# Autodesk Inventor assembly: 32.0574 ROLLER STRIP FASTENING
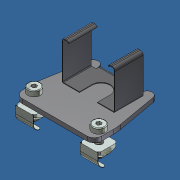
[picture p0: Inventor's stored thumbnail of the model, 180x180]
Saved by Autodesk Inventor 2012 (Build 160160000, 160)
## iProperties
Created: 2013-04
Part Number: 32.0574 ROLLER STRIP FASTENING
Document SubType Name: Assembly
Designer: Admin
Author: Admin
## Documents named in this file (5)
- C:\Andys Backup Data\ANDY'S INVENTOR\INVENTOR LIBRARIES\PARTS LIBRARY\KANBAN SYSTEMS\32.0574 ROLLER STRIP FASTENING.iam
- C:\Andys Backup Data\ANDY'S INVENTOR\INVENTOR LIBRARIES\PARTS LIBRARY\KANBAN SYSTEMS\SUBCOMPONENTS\32.0574 BASE PLATE.ipt
- C:\Andys Backup Data\ANDY'S INVENTOR\INVENTOR LIBRARIES\PARTS LIBRARY\KANBAN SYSTEMS\SUBCOMPONENTS\32.0574 CLIP.ipt
- C:\Andys Backup Data\ANDY'S INVENTOR\INVENTOR LIBRARIES\PARTS LIBRARY\FASTENING ELEMENTS\SCREWS CAP\21.1235 M5X16.ipt
- C:\Andys Backup Data\ANDY'S INVENTOR\INVENTOR LIBRARIES\PARTS LIBRARY\FASTENING ELEMENTS\NUTS\21.1320_2 M5 SQUARE NUT POS FXG.ipt
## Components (6 placed, 4 different names)
1. 32.0574 BASE PLATE:1 — Mate:1, Mate:2, Angle:1, Flush:1, Insert:1, Insert:2, Mate:5, Mate:6, Angle:2, Angle:3
2. 32.0574 CLIP:1 — Mate:1, Mate:2, Angle:1, Flush:1
3. 21.1235  M5 x 16:1 — Insert:1, Mate:3
4. 21.1235  M5 x 16:2 — Insert:2, Mate:4
5. 21.1320_2 M5 SQUARE NUT POS FXG:1 — Mate:3, Mate:5, Angle:3
6. 21.1320_2 M5 SQUARE NUT POS FXG:2 — Mate:4, Mate:6, Angle:2
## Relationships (12: Mate 6, Angle 3, Insert 2, Flush 1)
- Mate:1: 32.0574 BASE PLATE:1 ↔ 32.0574 CLIP:1
- Mate:2: 32.0574 BASE PLATE:1 ↔ 32.0574 CLIP:1
- Angle:1: 32.0574 BASE PLATE:1 ↔ 32.0574 CLIP:1
- Flush:1: 32.0574 BASE PLATE:1 ↔ 32.0574 CLIP:1
- Insert:1: 32.0574 BASE PLATE:1 ↔ 21.1235  M5 x 16:1
- Insert:2: 32.0574 BASE PLATE:1 ↔ 21.1235  M5 x 16:2
- Mate:3: 21.1235  M5 x 16:1 ↔ 21.1320_2 M5 SQUARE NUT POS FXG:1
- Mate:4: 21.1235  M5 x 16:2 ↔ 21.1320_2 M5 SQUARE NUT POS FXG:2
- Mate:5: 32.0574 BASE PLATE:1 ↔ 21.1320_2 M5 SQUARE NUT POS FXG:1
- Mate:6: 32.0574 BASE PLATE:1 ↔ 21.1320_2 M5 SQUARE NUT POS FXG:2
- Angle:2: 32.0574 BASE PLATE:1 ↔ 21.1320_2 M5 SQUARE NUT POS FXG:2
- Angle:3: 32.0574 BASE PLATE:1 ↔ 21.1320_2 M5 SQUARE NUT POS FXG:1
